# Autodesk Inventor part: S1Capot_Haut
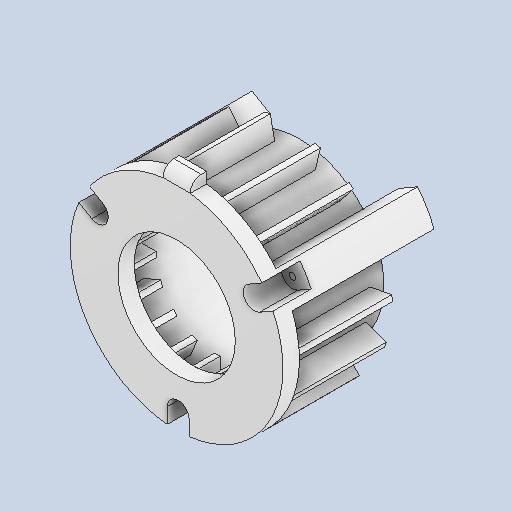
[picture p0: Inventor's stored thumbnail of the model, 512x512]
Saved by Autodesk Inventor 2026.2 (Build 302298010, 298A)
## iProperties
Created: 1601-01
Part Number: S1Capot_Haut
Material: ABS
Document SubType Name: Modeling
Designer: mel
Density: 1.02 g/cm^3
Appearance: white-pw-mt11050
Author: mel
Sending System: SOLIDWORKS 2023
Part Number: Capot_Haut
Last Saved Date: 2025-04-02
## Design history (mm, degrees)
feature "Enlèv. mat.-Extru.2"
node "Solide1"
